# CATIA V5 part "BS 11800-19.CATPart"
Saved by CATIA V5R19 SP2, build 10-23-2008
Part number: BS 11800-19
Bounding box of the stored display mesh (mm): x -74.81 to 74.81, y -74.81 to 74.81, z 0 to 116
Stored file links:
  C:\Users\Bora\Desktop\3D Katı model\BS serisi\BS 11800\BS 11800-19.CATPart
  C:\Program Files\Dassault Systemes\B19\intel_a\reffiles\standard\MetricThickPitch.txt
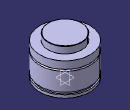
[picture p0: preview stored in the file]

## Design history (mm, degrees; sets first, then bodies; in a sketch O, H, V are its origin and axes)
Body1 (main body)
  Sketch1 on yz-plane, origin (0, 0, 0), H (0, 1, 0), V (0, 0, 1)
    point P1 (75, 74)
    point P2 (75, 69)
    point P5 (50, 115)
    point P7 (50, 115)
    point P12 (75, 69)
    point P13 (75, 74)
    arc A1 centre (75, 71.5) radius 2.5 from (75, 74) to (75, 69) ccw
    line L1 (75, 0) -> (75, 8)
    line L2 (50, 115) -> (50, 96)
    arc A2 centre (49, 115) radius 1 from (50, 115) to (49, 116) ccw
    line L3 (71, 15) -> (71, 8)
    line L4 (75, 15) -> (75, 69)
    line L5 (75, 74) -> (75, 96)
    line L6 (49, 116) -> (0, 116)
    point P15 (0, 116)
    line L7 (50, 96) -> (75, 96)
    line L8 (0, 0) -> (75, 0)
    line L9 (71, 15) -> (75, 15)
    line L10 (71, 8) -> (75, 8)
    coincidence: P15 V, P1 P13, P2 P12, P5 P7
    tangency: L6 A2
    horizontal: L7 H, L8 H, L9 H, L10 H
  Shaft1: profile Sketch1, axis Sketch1.V, angle 360
  Sketch2 on face of Shaft1 from Sketch1.L8, origin (0, 0, 0), H (1, 0, 0), V (0, -1, 0)
    point P1 (50, 0)
    distance P1 V = 50
  Hole1: placed by Sketch2, at (50, 0, 0) direction (0, 0, 1), diameter 8.376, depth 12, threaded "M10", thread diameter 10, thread depth 12, pitch 1.5
  CircPattern1: of Hole1, instances 4, angular step 90, axis from xy-plane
